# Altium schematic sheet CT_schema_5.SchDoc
size 350 x 348 mm
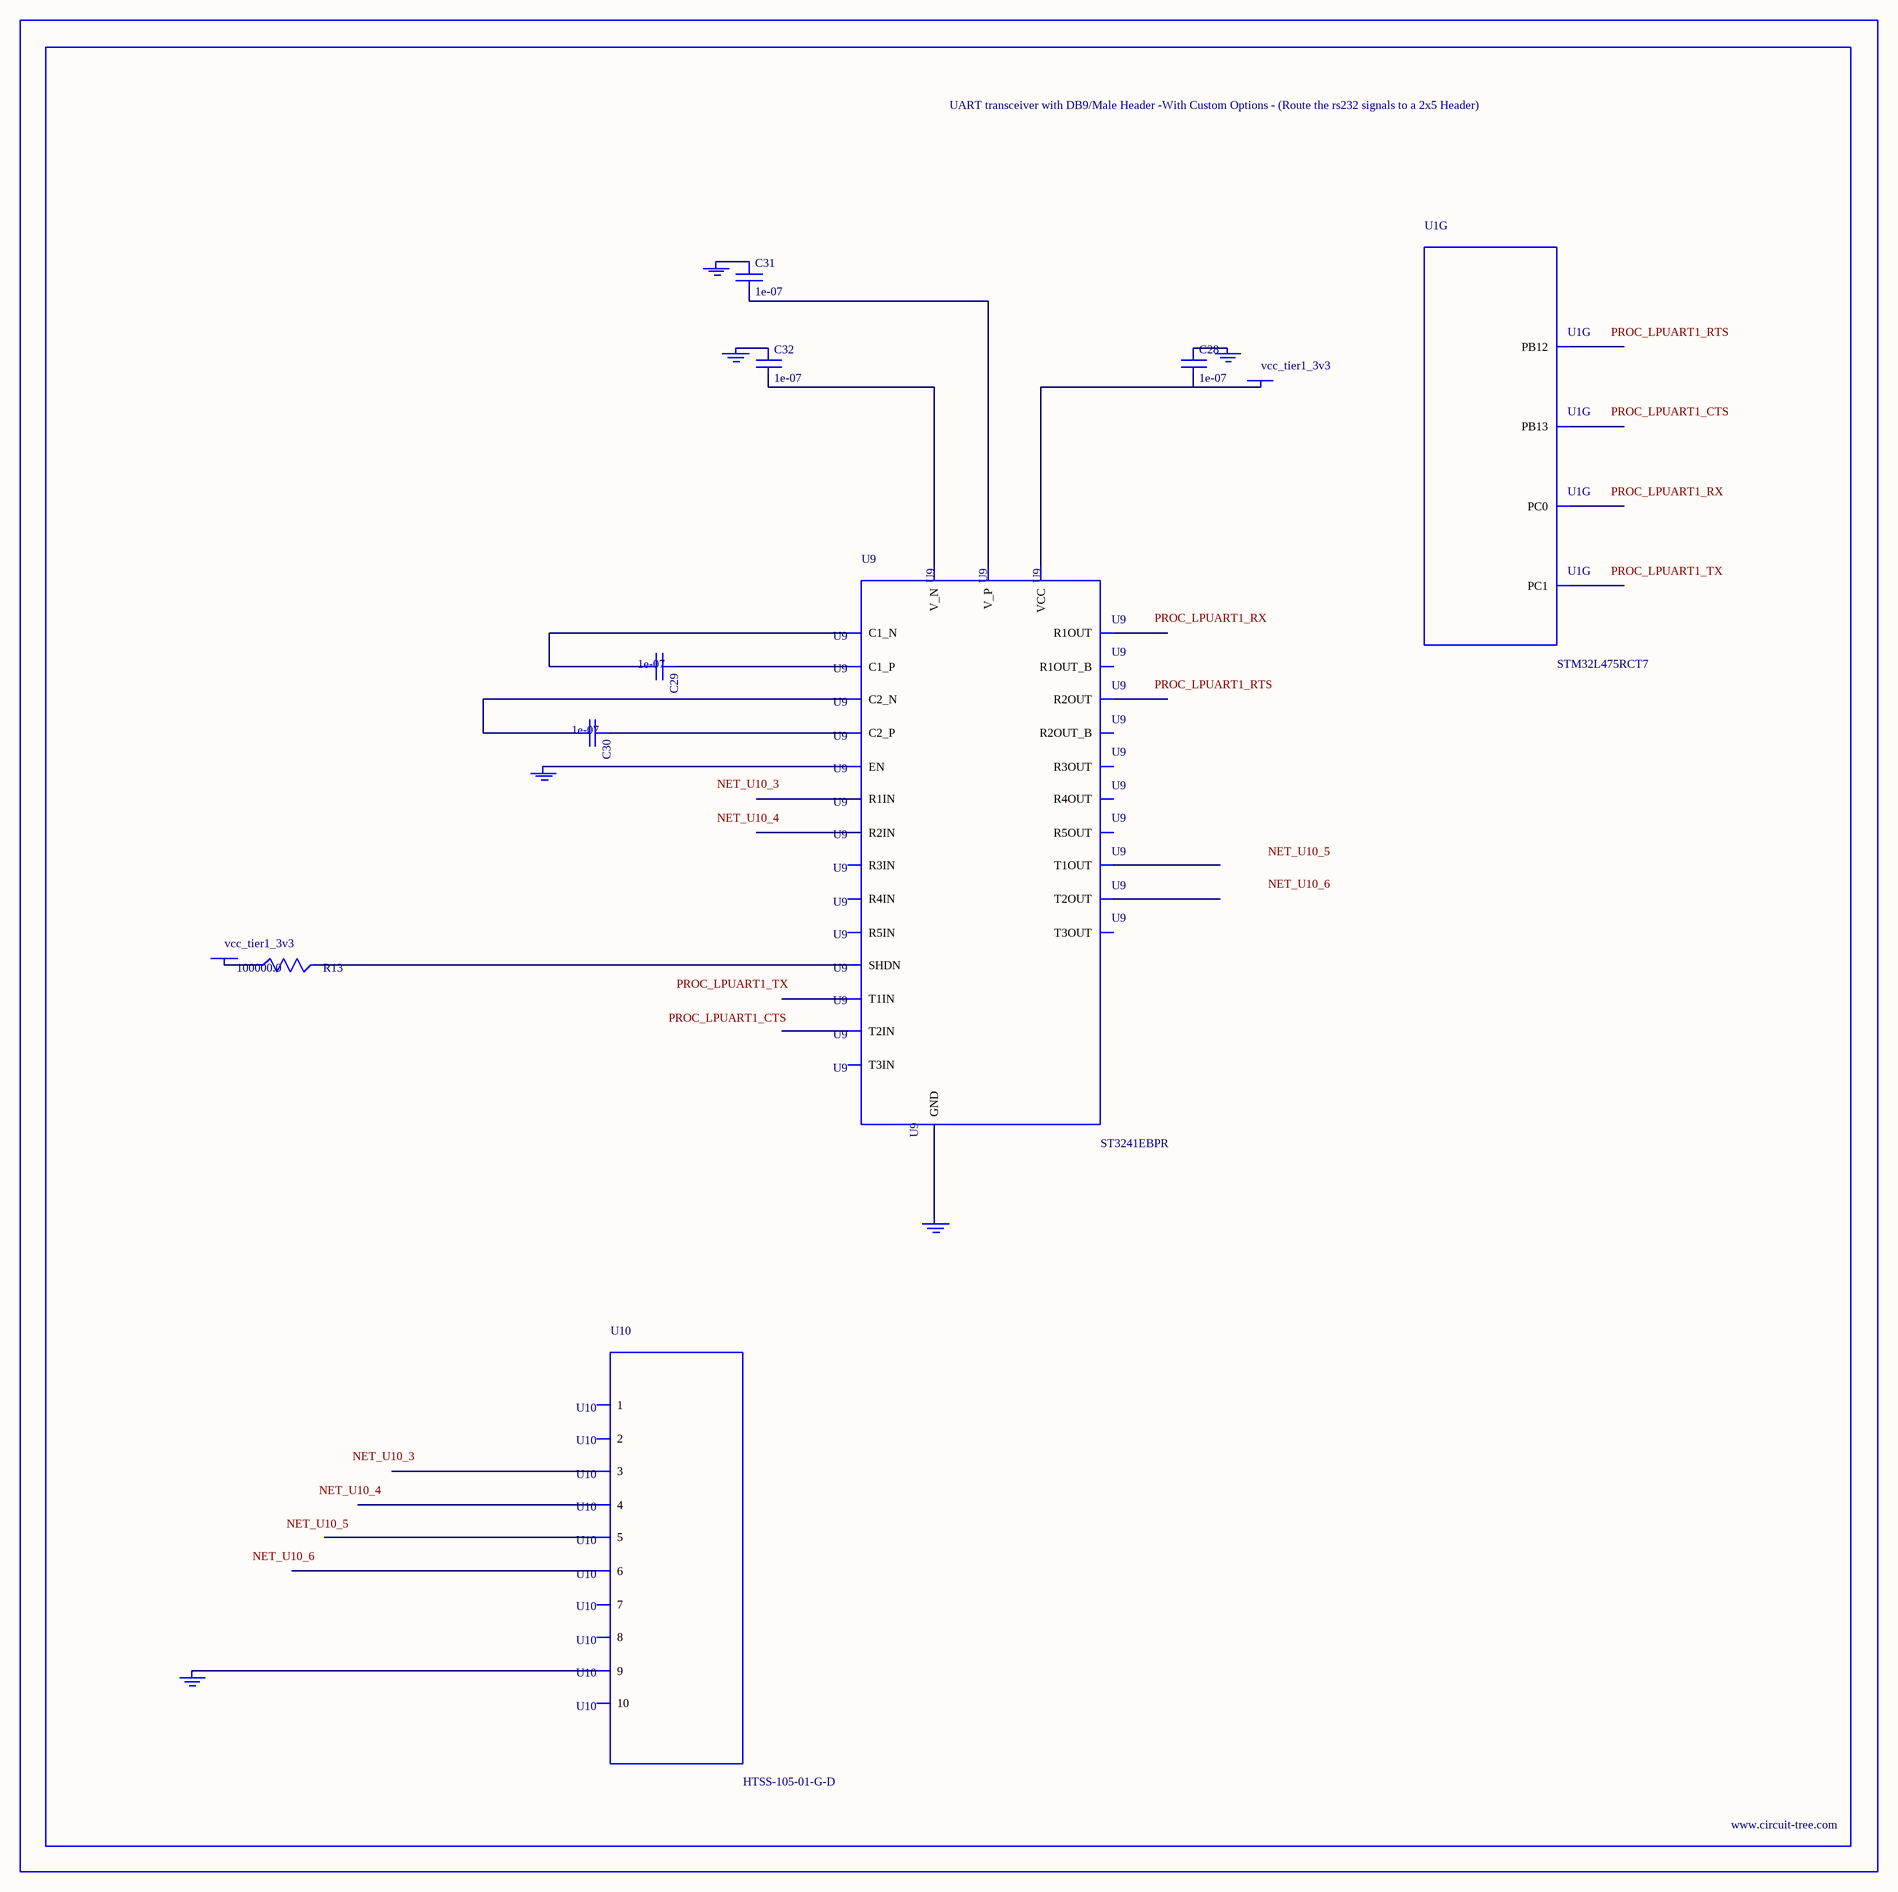
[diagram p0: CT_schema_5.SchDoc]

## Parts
BORDER4  (no value)
C28  1e-07  [C0402]
C29  1e-07  [C0402]
C30  1e-07  [C0402]
C31  1e-07  [C0402]
C32  1e-07  [C0402]
GND_INSTANCE_4_0  (no value)
GND_INSTANCE_4_1  (no value)
GND_INSTANCE_4_2  (no value)
GND_INSTANCE_4_3  (no value)
GND_INSTANCE_4_4  (no value)
GND_INSTANCE_4_5  (no value)
POWER_INSTANCE_4_0  vcc_tier1_3v3
POWER_INSTANCE_4_1  vcc_tier1_3v3
R13  100000.0  [R0603]
U1  STM32L475RCT7  [LQFP64]  (part G of 8)
U9  ST3241EBPR  [SSOP-28]
U10  HTSS-105-01-G-D  [HTSS-105-01-G-D]

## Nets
NetC28_1: C28.1 GND_INSTANCE_4_2.0(GND)
NetC28_2: C28.2 POWER_INSTANCE_4_1.0(PWR) U9.26(VCC)
NetC29_1: C29.1 U9.28(C1_P)
NetC29_2: C29.2 U9.24(C1_N)
NetC30_1: C30.1 U9.1(C2_P)
NetC30_2: C30.2 U9.2(C2_N)
NetC31_1: C31.1 GND_INSTANCE_4_3.0(GND)
NetC31_2: C31.2 U9.27(V_P)
NetC32_1: C32.1 GND_INSTANCE_4_0.0(GND)
NetC32_2: C32.2 U9.3(V_N)
NetGND_INSTANCE_4_1_0: GND_INSTANCE_4_1.0(GND) U9.23(EN)
NetGND_INSTANCE_4_4_0: GND_INSTANCE_4_4.0(GND) U9.25(GND)
NetGND_INSTANCE_4_5_0: GND_INSTANCE_4_5.0(GND) U10.9
NetPOWER_INSTANCE_4_0_0: POWER_INSTANCE_4_0.0(PWR) R13.1
NetR13_2: R13.2 U9.22(SHDN)

Not connected (* = marked no-connect by the designer): U1 8(PC0) 9(PC1) 33(PB12) 34(PB13); U9 4(R1IN) 5(R2IN) 6(R3IN) 7(R4IN) 8(R5IN) 9(T1OUT) 10(T2OUT) 11(T3OUT) 12(T3IN) 13(T2IN) 14(T1IN) 15(R5OUT) 16(R4OUT) 17(R3OUT) 18(R2OUT) 19(R1OUT) 20(R2OUT_B) 21(R1OUT_B); U10 1 2 3 4 5 6 7 8 10

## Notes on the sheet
- Labels drawn without touching a wire or pin: NET_U10_3, NET_U10_4, NET_U10_5, NET_U10_6, PROC_LPUART1_CTS, PROC_LPUART1_RTS, PROC_LPUART1_RX, PROC_LPUART1_TX

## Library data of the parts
BORDER4 = BORDER_PAGE4
C28-C32 = C0402C104K3RACTU
GND_INSTANCE_4_0-GND_INSTANCE_4_5 = GND
POWER_INSTANCE_4_0 POWER_INSTANCE_4_1 = PWR
R13 = RC0603JR-07100KL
